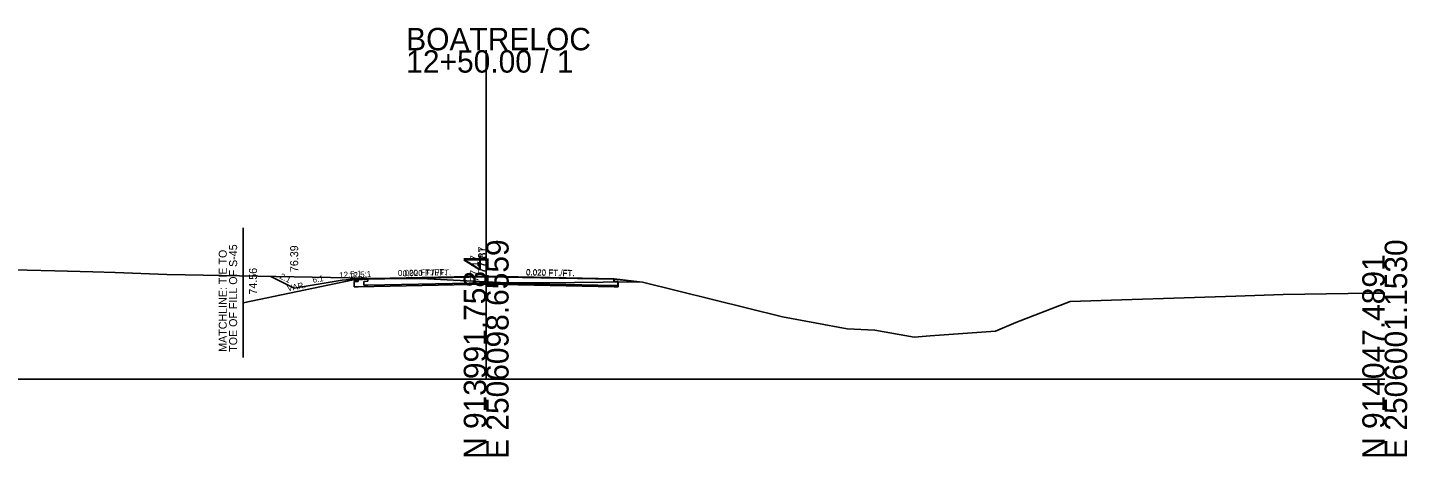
# Model space of a CAD drawing. Extents: x -26 to 403, y -10 to 2549.
# Drawn here: x 142.7 to 315.1, y 1490.3 to 1544 of the extents above; entities that cross this region are included whole.
import ezdxf

# ---------------------------------------------------------------- set-up
doc = ezdxf.new("R2010")
doc.units = 0
for name, color, linetype in [('RD_GPK_XS_Cell', 7, 'Continuous'), ('RD_Sketch9', 7, 'Continuous'), ('RD_XS_EarthShd', 7, 'Continuous'), ('RD_XS_ExGround', 7, 'Continuous'), ('RD_XS_Pave', 7, 'Continuous'), ('RD_XS_PaveOvlay', 7, 'Continuous'), ('RD_XS_TieSlope', 7, 'Continuous'), ('RD_XS_TX_Elev_EX', 7, 'Continuous'), ('RD_XS_TX_Elev_PR', 7, 'Continuous'), ('RD_XS_TX_ShdSlope', 7, 'Continuous'), ('RD_XS_TX_Slope', 7, 'Continuous')]:
    doc.layers.add(name, color=color, linetype=linetype)

msp = doc.modelspace()

# ---------------------------------------------------------------- linework, layer by layer
at = {"layer": 'RD_GPK_XS_Cell'}
for p, q in [((200, 1500), (200, 1541.16)), ((0, 1500), (200, 1500)), ((200, 1500), (312.31, 1500))]:
    msp.add_line(p, q, dxfattribs=at)
at = {"layer": 'RD_Sketch9'}
for p, q in [((176, 1511.39), (173.08, 1512.85)), ((184, 1512.55), (182, 1512.39)), ((184, 1512.55), (200, 1512.87)), ((184, 1512.22), (184, 1512.55)), ((200, 1512.87), (216, 1512.55)), ((216, 1512.55), (219.55, 1512.13)), ((216, 1512.22), (216, 1512.55)), ((182, 1512.39), (176, 1511.39)), ((183.5, 1512.21), (184, 1512.22)), ((183.5, 1511.54), (183.5, 1512.21)), ((184, 1511.55), (183.5, 1511.54)), ((184, 1511.55), (200, 1511.87)), ((200, 1511.87), (216, 1511.55)), ((216.5, 1512.21), (216, 1512.22)), ((216, 1511.55), (216.5, 1511.54)), ((216.5, 1511.54), (216.5, 1512.21))]:
    msp.add_line(p, q, dxfattribs=at)
at = {"layer": 'RD_XS_EarthShd'}
for p, q in [((185.21, 1512.52), (183.21, 1512.36)), ((215.97, 1512.49), (219.55, 1512.13))]:
    msp.add_line(p, q, dxfattribs=at)
at = {"layer": 'RD_XS_ExGround'}
for p, q in [((139.14, 1513.72), (146.09, 1513.55)), ((146.09, 1513.55), (150.83, 1513.44)), ((150.83, 1513.44), (153.64, 1513.34)), ((153.64, 1513.34), (160.09, 1513.09)), ((160.09, 1513.09), (185.08, 1512.64)), ((185.08, 1512.64), (188.07, 1512.6)), ((188.07, 1512.6), (192.68, 1512.55)), ((192.68, 1512.55), (200, 1512.17)), ((200, 1512.17), (202.67, 1512.03)), ((202.67, 1512.03), (207.47, 1512.05)), ((207.47, 1512.05), (218.21, 1512.17)), ((218.21, 1512.17), (218.81, 1512.15)), ((218.81, 1512.15), (219.55, 1512.13)), ((219.55, 1512.13), (237.03, 1507.77)), ((266.21, 1507.09), (273, 1509.69)), ((273, 1509.69), (293.72, 1510.39)), ((293.72, 1510.39), (299.6, 1510.59)), ((299.6, 1510.59), (310.43, 1510.74)), ((310.43, 1510.74), (312.31, 1510.77)), ((237.03, 1507.77), (245.12, 1506.29)), ((245.12, 1506.29), (248.58, 1506.1)), ((248.58, 1506.1), (253.51, 1505.23)), ((255.49, 1505.41), (263.64, 1506)), ((263.64, 1506), (266.21, 1507.09)), ((253.51, 1505.23), (255.49, 1505.41))]:
    msp.add_line(p, q, dxfattribs=at)
at = {"layer": 'RD_XS_Pave'}
for p, q in [((184.71, 1512.23), (185.21, 1512.24)), ((184.71, 1511.75), (184.71, 1512.23)), ((185.21, 1511.76), (184.71, 1511.75)), ((185.21, 1512.24), (185.21, 1512.52)), ((185.21, 1511.76), (200, 1512.05)), ((200, 1512.05), (215.97, 1511.73)), ((215.97, 1512.21), (215.97, 1512.49)), ((216.47, 1512.2), (215.97, 1512.21)), ((215.97, 1511.73), (216.47, 1511.72)), ((216.47, 1511.72), (216.47, 1512.2))]:
    msp.add_line(p, q, dxfattribs=at)
at = {"layer": 'RD_XS_PaveOvlay'}
for p, q in [((185.21, 1512.52), (200, 1512.81)), ((200, 1512.81), (215.97, 1512.49))]:
    msp.add_line(p, q, dxfattribs=at)
at = {"layer": 'RD_XS_TieSlope'}
for p, q in [((169.61, 1502.68), (169.61, 1518.91)), ((183.21, 1512.36), (169.61, 1509.56))]:
    msp.add_line(p, q, dxfattribs=at)

# ---------------------------------------------------------------- texts
at = {"layer": 'RD_GPK_XS_Cell'}
for s, p in [('BOATRELOC', (190, 1541.16)), ('12+50.00 / 1', (190, 1538.36))]:
    msp.add_text(s, height=2.8, dxfattribs=at).set_placement(p)
for s, p in [('E 2506098.6559', (202.8, 1490)), ('E 2506001.1530', (315.11, 1490)), ('N 913991.7584', (200, 1490)), ('N 914047.4891', (312.31, 1490))]:
    msp.add_text(s, height=2.8, rotation=90, dxfattribs=at).set_placement(p)
at = {"layer": 'RD_Sketch9'}
for s, height, rotation, p in [('76.39', 1, 90, (176.5, 1513.39)), (' 77.87', 1, 90, (200, 1512.87)), (' 77.87', 1, 90, (200, 1512.87)), ('2:1', 0.75, 333.4349, (174.1, 1512.62)), ('6:1', 0.75, 9.4623, (178.35, 1512.04)), ('12.5:1', 0.75, 4.5739, (181.66, 1512.62)), ('0.020 FT./FT.', 0.75, 1.1458, (188.97, 1512.9)), ('0.020 FT./FT.', 0.75, 358.8542, (204.98, 1513.03))]:
    msp.add_text(s, height=height, rotation=rotation, dxfattribs=at).set_placement(p)
at = {"layer": 'RD_XS_TX_Elev_EX'}
msp.add_text('77.17', height=1, rotation=90, dxfattribs=at).set_placement((199, 1512.17))
at = {"layer": 'RD_XS_TX_Elev_PR'}
for s, p in [('MATCHLINE: TIE TO', (167.57, 1503.41)), ('TOE OF FILL OF S-45', (168.87, 1503.41)), (' 77.81', (200, 1512.81)), ('74.56', (171.35, 1510.57))]:
    msp.add_text(s, height=1, rotation=90, dxfattribs=at).set_placement(p)
at = {"layer": 'RD_XS_TX_ShdSlope'}
msp.add_text('12.5:1', height=0.75, rotation=4.5739, dxfattribs=at).set_placement((182.88, 1512.58))
at = {"layer": 'RD_XS_TX_Slope'}
for s, rotation, p in [('0.020 FT./FT.', 1.1458, (189.57, 1512.85)), ('0.020 FT./FT.', 358.8542, (204.96, 1512.96)), ('VAR.', 11.5247, (175.2, 1510.97))]:
    msp.add_text(s, height=0.75, rotation=rotation, dxfattribs=at).set_placement(p)

doc.saveas('drawing.dxf')
